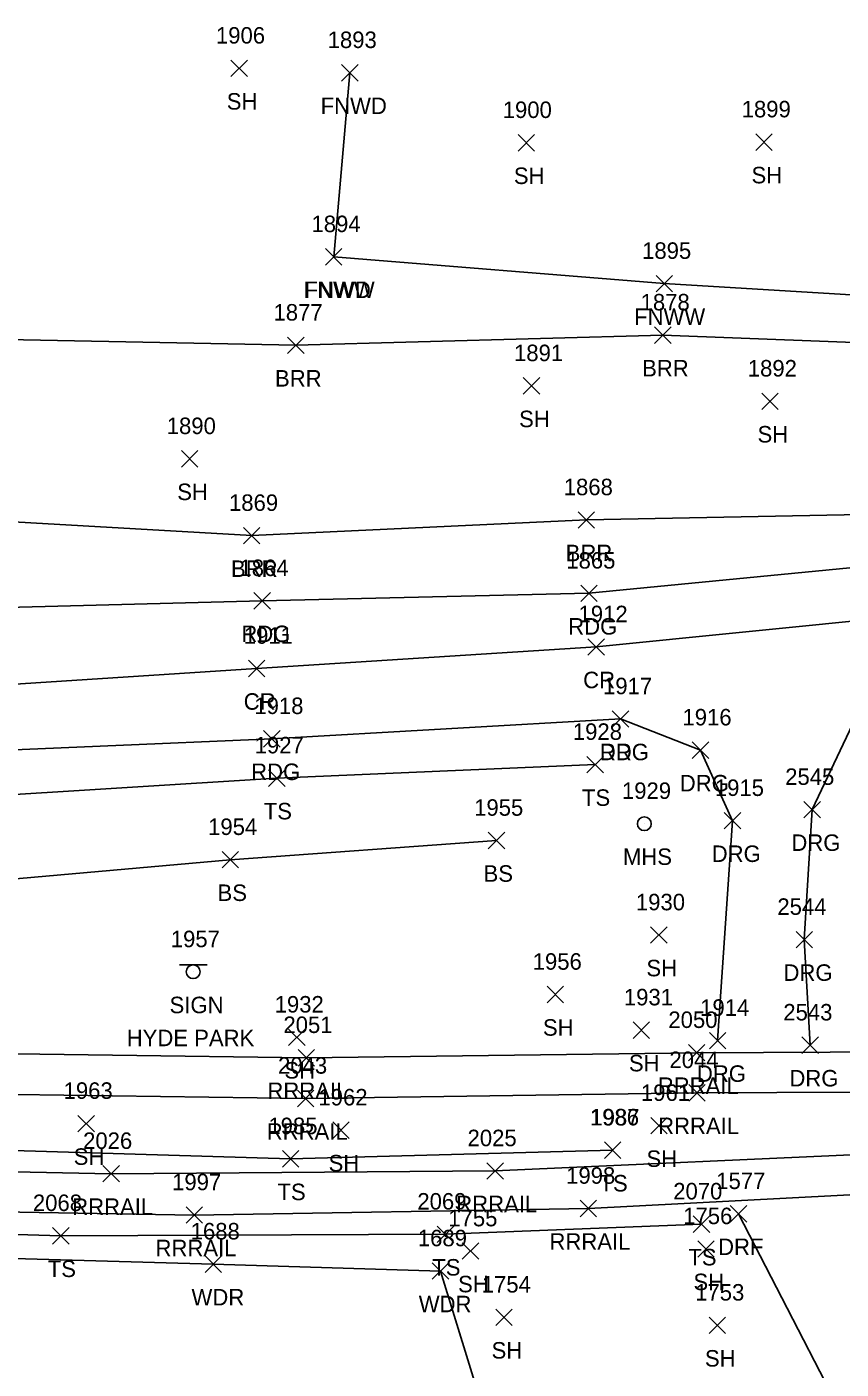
# Model space of a CAD drawing. Extents: x 1609623 to 1616187, y 756677 to 762826.
# Drawn here: x 1610145.1 to 1610243.7, y 761799.9 to 761962.6 of the extents above; entities that cross this region are included whole.
import ezdxf

# ---------------------------------------------------------------- set-up
doc = ezdxf.new("R2010")
doc.units = 0
for name, color, linetype in [('L_A', 7, 'Continuous'), ('L_I', 7, 'Continuous'), ('L_TIC', 7, 'Continuous'), ('LABL', 7, 'Continuous'), ('LAWA', 7, 'Continuous'), ('LELB', 7, 'Continuous'), ('LFNC', 7, 'Continuous'), ('P_A', 7, 'Continuous'), ('P_I', 7, 'Continuous'), ('P_TIC', 7, 'Continuous'), ('PEU', 7, 'Continuous'), ('PRC', 7, 'Continuous'), ('R_A', 7, 'Continuous'), ('R_I', 7, 'Continuous'), ('R_TIC', 7, 'Continuous'), ('RDF', 7, 'Continuous'), ('RDG', 7, 'Continuous'), ('RR', 7, 'Continuous'), ('S_A', 7, 'Continuous'), ('S_C', 7, 'Continuous'), ('S_I', 7, 'Continuous'), ('SSGN', 7, 'Continuous'), ('U_A', 7, 'Continuous'), ('U_I', 7, 'Continuous'), ('USMH', 7, 'Continuous')]:
    doc.layers.add(name, color=color, linetype=linetype)

msp = doc.modelspace()

# ---------------------------------------------------------------- linework, layer by layer
at = {"layer": 'L_TIC'}
for points in [[(1610169.82, 761956.59), (1610171.82, 761958.59)], [(1610171.82, 761956.59), (1610169.82, 761958.59)], [(1610183.22, 761956.05), (1610185.22, 761958.05)], [(1610185.22, 761956.05), (1610183.22, 761958.05)], [(1610204.59, 761947.57), (1610206.59, 761949.57)], [(1610206.59, 761947.57), (1610204.59, 761949.57)], [(1610233.37, 761947.65), (1610235.37, 761949.65)], [(1610235.37, 761947.65), (1610233.37, 761949.65)], [(1610181.26, 761933.74), (1610183.26, 761935.74)], [(1610183.26, 761933.74), (1610181.26, 761935.74)], [(1610181.26, 761933.74), (1610183.26, 761935.74)], [(1610183.26, 761933.74), (1610181.26, 761935.74)], [(1610221.3, 761930.5), (1610223.3, 761932.5)], [(1610223.3, 761930.5), (1610221.3, 761932.5)], [(1610221.12, 761924.25), (1610223.12, 761926.25)], [(1610223.12, 761924.25), (1610221.12, 761926.25)], [(1610176.67, 761923.02), (1610178.67, 761925.02)], [(1610178.67, 761923.02), (1610176.67, 761925.02)], [(1610205.22, 761918.1), (1610207.22, 761920.1)], [(1610207.22, 761918.1), (1610205.22, 761920.1)], [(1610234.1, 761916.24), (1610236.1, 761918.24)], [(1610236.1, 761916.24), (1610234.1, 761918.24)], [(1610163.82, 761909.26), (1610165.82, 761911.26)], [(1610165.82, 761909.26), (1610163.82, 761911.26)], [(1610211.86, 761901.85), (1610213.86, 761903.85)], [(1610213.86, 761901.85), (1610211.86, 761903.85)], [(1610171.33, 761899.95), (1610173.33, 761901.95)], [(1610173.33, 761899.95), (1610171.33, 761901.95)], [(1610212.92, 761872.2), (1610214.92, 761874.2)], [(1610214.92, 761872.2), (1610212.92, 761874.2)], [(1610174.38, 761870.56), (1610176.38, 761872.56)], [(1610176.38, 761870.56), (1610174.38, 761872.56)], [(1610200.97, 761863), (1610202.97, 761865)], [(1610202.97, 761863), (1610200.97, 761865)], [(1610168.74, 761860.67), (1610170.74, 761862.67)], [(1610170.74, 761860.67), (1610168.74, 761862.67)], [(1610220.64, 761851.54), (1610222.64, 761853.54)], [(1610222.64, 761851.54), (1610220.64, 761853.54)], [(1610208.11, 761844.34), (1610210.11, 761846.34)], [(1610210.11, 761844.34), (1610208.11, 761846.34)], [(1610176.8, 761839.15), (1610178.8, 761841.15)], [(1610178.8, 761839.15), (1610176.8, 761841.15)], [(1610218.52, 761840.02), (1610220.52, 761842.02)], [(1610220.52, 761840.02), (1610218.52, 761842.02)], [(1610151.29, 761828.69), (1610153.29, 761830.69)], [(1610153.29, 761828.69), (1610151.29, 761830.69)], [(1610182.15, 761827.89), (1610184.15, 761829.89)], [(1610184.15, 761827.89), (1610182.15, 761829.89)], [(1610220.65, 761828.44), (1610222.65, 761830.44)], [(1610222.65, 761828.44), (1610220.65, 761830.44)], [(1610176.04, 761824.41), (1610178.04, 761826.41)], [(1610178.04, 761824.41), (1610176.04, 761826.41)], [(1610215.04, 761825.47), (1610217.04, 761827.47)], [(1610217.04, 761825.47), (1610215.04, 761827.47)], [(1610215.04, 761825.46), (1610217.04, 761827.46)], [(1610217.04, 761825.46), (1610215.04, 761827.46)], [(1610225.8, 761816.5), (1610227.8, 761818.5)], [(1610227.8, 761816.5), (1610225.8, 761818.5)], [(1610148.22, 761815.09), (1610150.22, 761817.09)], [(1610150.22, 761815.09), (1610148.22, 761817.09)], [(1610194.79, 761815.27), (1610196.79, 761817.27)], [(1610196.79, 761815.27), (1610194.79, 761817.27)], [(1610197.83, 761813.24), (1610199.83, 761815.24)], [(1610199.83, 761813.24), (1610197.83, 761815.24)], [(1610226.34, 761813.5), (1610228.34, 761815.5)], [(1610228.34, 761813.5), (1610226.34, 761815.5)], [(1610166.68, 761811.65), (1610168.68, 761813.65)], [(1610168.68, 761811.65), (1610166.68, 761813.65)], [(1610194.19, 761810.82), (1610196.19, 761812.82)], [(1610196.19, 761810.82), (1610194.19, 761812.82)], [(1610201.89, 761805.21), (1610203.89, 761807.21)], [(1610203.89, 761805.21), (1610201.89, 761807.21)], [(1610227.73, 761804.24), (1610229.73, 761806.24)], [(1610229.73, 761804.24), (1610227.73, 761806.24)]]:
    msp.add_lwpolyline(points, dxfattribs=at)
at = {"layer": 'LABL'}
msp.add_lwpolyline([(1610248.25, 761903.55), (1610212.86, 761902.85), (1610172.33, 761900.95), (1610131.44, 761903.3), (1610100.93, 761896.76), (1610074.3, 761892.77), (1610070.02, 761901.24), (1610088.05, 761924.14), (1610103.11, 761932.23), (1610130.22, 761924.96), (1610177.67, 761924.02), (1610222.12, 761925.25), (1610272.69, 761923.3), (1610298.02, 761931.54), (1610307.47, 761946.97), (1610343.23, 761952.19), (1610333.93, 761931.55), (1610306.47, 761919.59), (1610275.72, 761908.1)], dxfattribs=at)
at = {"layer": 'LAWA'}
msp.add_lwpolyline([(1610105.26, 761813.02), (1610140.61, 761813.42), (1610167.68, 761812.65), (1610195.19, 761811.82), (1610200.47, 761794.62), (1610201.65, 761767.6), (1610187.83, 761765.14), (1610147.91, 761771.28), (1610109.49, 761778.29), (1610068.49, 761778.93), (1610059.44, 761777.35), (1610050.54, 761771.19), (1610026.67, 761771.55), (1610012.41, 761775.03), (1609988.62, 761770.46), (1609964.66, 761759.68), (1609934.55, 761749.72), (1609900.52, 761743.76), (1609861.36, 761735.79), (1609834.63, 761731.47), (1609803.94, 761726.14)], dxfattribs=at)
at = {"layer": 'LELB'}
for points in [[(1610013.78, 761861.49), (1610053.03, 761867.24), (1610097.84, 761870.5), (1610137.8, 761869.22), (1610175.38, 761871.56), (1610213.92, 761873.2)], [(1609808.99, 761869.38), (1609856.47, 761857.61), (1609895.17, 761849.99), (1609941.57, 761842.59), (1609980.54, 761837.23), (1610021.92, 761832.42), (1610061.45, 761828.82), (1610098.2, 761827.1), (1610138.02, 761826.61), (1610177.04, 761825.41), (1610216.04, 761826.47), (1610216.04, 761826.46)], [(1610091.03, 761859.31), (1610128.23, 761857.97), (1610169.74, 761861.67), (1610201.97, 761864)], [(1609853.79, 761850.29), (1609899.31, 761840.85), (1609947.61, 761833.03), (1609998.93, 761826.28), (1610045.2, 761821.51), (1610074.6, 761819.05), (1610109.29, 761817.31), (1610149.22, 761816.09), (1610195.79, 761816.27), (1610226.8, 761817.5)]]:
    msp.add_lwpolyline(points, dxfattribs=at)
at = {"layer": 'LFNC'}
for points in [[(1610184.22, 761957.05), (1610182.26, 761934.74)], [(1610182.26, 761934.74), (1610222.3, 761931.5), (1610278.21, 761928.1), (1610278.74, 761949.49)]]:
    msp.add_lwpolyline(points, dxfattribs=at)
at = {"layer": 'P_TIC'}
for points in [[(1610212.17, 761892.96), (1610214.17, 761894.96)], [(1610214.17, 761892.96), (1610212.17, 761894.96)], [(1610172.59, 761892.05), (1610174.59, 761894.05)], [(1610174.59, 761892.05), (1610172.59, 761894.05)], [(1610213.04, 761886.46), (1610215.04, 761888.46)], [(1610215.04, 761886.46), (1610213.04, 761888.46)], [(1610171.93, 761883.85), (1610173.93, 761885.85)], [(1610173.93, 761883.85), (1610171.93, 761885.85)], [(1610216, 761877.73), (1610218, 761879.73)], [(1610218, 761877.73), (1610216, 761879.73)], [(1610173.77, 761875.33), (1610175.77, 761877.33)], [(1610175.77, 761875.33), (1610173.77, 761877.33)]]:
    msp.add_lwpolyline(points, dxfattribs=at)
at = {"layer": 'PEU'}
for points in [[(1610061.53, 761886.05), (1610095.83, 761889.43), (1610133.36, 761892.01), (1610173.59, 761893.05), (1610213.17, 761893.96), (1610248.92, 761897.46)], [(1610217, 761878.73), (1610174.77, 761876.33), (1610133.16, 761874.56), (1610094.41, 761873.65), (1610052.62, 761869.93), (1610013.35, 761867.91)]]:
    msp.add_lwpolyline(points, dxfattribs=at)
at = {"layer": 'PRC'}
msp.add_lwpolyline([(1610012.87, 761874.99), (1610052.18, 761877.05), (1610092.88, 761880.29), (1610131.85, 761882.19), (1610172.93, 761884.85), (1610214.04, 761887.46), (1610250.72, 761891.17)], dxfattribs=at)
at = {"layer": 'R_TIC'}
for points in [[(1610216, 761877.73), (1610218, 761879.73)], [(1610218, 761877.73), (1610216, 761879.73)], [(1610225.68, 761873.95), (1610227.68, 761875.95)], [(1610227.68, 761873.95), (1610225.68, 761875.95)], [(1610239.2, 761866.74), (1610241.2, 761868.74)], [(1610241.2, 761866.74), (1610239.2, 761868.74)], [(1610229.55, 761865.4), (1610231.55, 761867.4)], [(1610231.55, 761865.4), (1610229.55, 761867.4)], [(1610238.25, 761850.99), (1610240.25, 761852.99)], [(1610240.25, 761850.99), (1610238.25, 761852.99)], [(1610225.22, 761837.28), (1610227.22, 761839.28)], [(1610227.22, 761837.28), (1610225.22, 761839.28)], [(1610227.76, 761838.75), (1610229.76, 761840.75)], [(1610229.76, 761838.75), (1610227.76, 761840.75)], [(1610238.97, 761838.19), (1610240.97, 761840.19)], [(1610240.97, 761838.19), (1610238.97, 761840.19)], [(1610177.94, 761836.67), (1610179.94, 761838.67)], [(1610179.94, 761836.67), (1610177.94, 761838.67)], [(1610225.26, 761832.42), (1610227.26, 761834.42)], [(1610227.26, 761832.42), (1610225.26, 761834.42)], [(1610177.86, 761831.74), (1610179.86, 761833.74)], [(1610179.86, 761831.74), (1610177.86, 761833.74)], [(1610154.3, 761822.62), (1610156.3, 761824.62)], [(1610156.3, 761822.62), (1610154.3, 761824.62)], [(1610200.81, 761822.95), (1610202.81, 761824.95)], [(1610202.81, 761822.95), (1610200.81, 761824.95)], [(1610212.1, 761818.4), (1610214.1, 761820.4)], [(1610214.1, 761818.4), (1610212.1, 761820.4)], [(1610230.28, 761817.76), (1610232.28, 761819.76)], [(1610232.28, 761817.76), (1610230.28, 761819.76)], [(1610164.38, 761817.61), (1610166.38, 761819.61)], [(1610166.38, 761817.61), (1610164.38, 761819.61)]]:
    msp.add_lwpolyline(points, dxfattribs=at)
at = {"layer": 'RDF'}
msp.add_lwpolyline([(1610264.31, 761756.11), (1610264.09, 761770.09), (1610248.38, 761785.61), (1610231.28, 761818.76)], dxfattribs=at)
at = {"layer": 'RDG'}
for points in [[(1610239.97, 761839.19), (1610239.25, 761851.99), (1610240.2, 761867.74), (1610246.98, 761882.07)], [(1610228.76, 761839.75), (1610230.55, 761866.4), (1610226.68, 761874.95), (1610217, 761878.73)]]:
    msp.add_lwpolyline(points, dxfattribs=at)
at = {"layer": 'RR'}
for points in [[(1610920.34, 761877.5), (1610875.2, 761880.63), (1610823.88, 761880.35), (1610770.14, 761877.16), (1610718.25, 761872.56), (1610624.39, 761862.75), (1610528.95, 761852.85), (1610433.45, 761843.38), (1610390.08, 761839.1), (1610343.15, 761834.31), (1610326.86, 761832.49), (1610295.2, 761829.73), (1610250.28, 761826.15), (1610201.81, 761823.95), (1610155.3, 761823.62), (1610106.26, 761824.63), (1610057.65, 761827.02), (1610007.52, 761831.91), (1609961.32, 761837.48), (1609915.47, 761844.69), (1609871.57, 761853.1), (1609828.18, 761862.73), (1609811.27, 761866.9)], [(1610356.77, 761837.2), (1610311.16, 761837.59), (1610274.66, 761838.51), (1610226.22, 761838.28), (1610178.94, 761837.67), (1610131.97, 761838.32), (1610083.45, 761840.67), (1610036.86, 761844.06), (1609989.49, 761848.51), (1609944.78, 761853.81), (1609900.87, 761860.46), (1609856.95, 761868.77), (1609813.49, 761878.61)], [(1609812.23, 761861.59), (1609849.51, 761852.68), (1609889.11, 761844.53), (1609934.67, 761836.61), (1609980.82, 761829.97), (1610026.24, 761824.91), (1610071.82, 761821.22), (1610118.39, 761819.39), (1610165.38, 761818.61), (1610213.1, 761819.4), (1610261.76, 761821.96), (1610309.94, 761826.07), (1610356.6, 761830.72), (1610389.15, 761834), (1610434.7, 761838.51), (1610480.7, 761843.13), (1610575.97, 761852.51), (1610672.94, 761862.83), (1610719.08, 761867.65), (1610767.25, 761871.97), (1610815.87, 761875.05), (1610864.69, 761875.82), (1610894.81, 761874.78)], [(1609812.59, 761873.79), (1609856.08, 761863.93), (1609900.7, 761855.53), (1609944.64, 761848.95), (1609989.39, 761843.6), (1610036.39, 761839.13), (1610083.14, 761835.83), (1610131.98, 761833.39), (1610178.86, 761832.74), (1610226.26, 761833.42), (1610274.6, 761833.63)]]:
    msp.add_lwpolyline(points, dxfattribs=at)
at = {"layer": 'SSGN'}
for p, q in [((1610163.59, 761848.92), (1610166.92, 761848.92)), ((1610165.24, 761848.09), (1610165.24, 761848.09))]:
    msp.add_line(p, q, dxfattribs=at)
msp.add_circle((1610165.24, 761848.09), 0.833, dxfattribs=at)
at = {"layer": 'USMH'}
for p, q in [((1610219.88, 761866.04), (1610219.88, 761866.04)), ((1610220.71, 761866.04), (1610220.71, 761866.04))]:
    msp.add_line(p, q, dxfattribs=at)
msp.add_circle((1610219.88, 761866.04), 0.833, dxfattribs=at)

# ---------------------------------------------------------------- texts
at = {"layer": 'L_A'}
for s, p in [('SH', (1610169.31, 761952.59)), ('FNWD', (1610180.68, 761952.05)), ('SH', (1610204.08, 761943.57)), ('SH', (1610232.86, 761943.65)), ('FNWW', (1610178.61, 761929.74)), ('FNWD', (1610178.73, 761929.74)), ('FNWW', (1610218.64, 761926.5)), ('BRR', (1610219.61, 761920.25)), ('BRR', (1610175.15, 761919.02)), ('SH', (1610204.71, 761914.1)), ('SH', (1610233.59, 761912.24)), ('SH', (1610163.31, 761905.26)), ('BRR', (1610210.35, 761897.85)), ('BRR', (1610169.82, 761895.95)), ('TS', (1610212.33, 761868.2)), ('TS', (1610173.79, 761866.56)), ('BS', (1610200.41, 761859)), ('BS', (1610168.19, 761856.67)), ('SH', (1610220.13, 761847.54)), ('SH', (1610207.6, 761840.34)), ('SH', (1610218.01, 761836.02)), ('SH', (1610176.29, 761835.15)), ('SH', (1610150.77, 761824.69)), ('SH', (1610220.14, 761824.44)), ('SH', (1610181.64, 761823.89)), ('TS', (1610214.45, 761821.47)), ('TS', (1610214.45, 761821.46)), ('TS', (1610175.45, 761820.41)), ('TS', (1610194.2, 761811.27)), ('TS', (1610225.21, 761812.5)), ('TS', (1610147.63, 761811.09)), ('SH', (1610197.32, 761809.24)), ('SH', (1610225.83, 761809.5)), ('WDR', (1610165.04, 761807.65)), ('WDR', (1610192.56, 761806.82)), ('SH', (1610201.38, 761801.21)), ('SH', (1610227.22, 761800.24))]:
    msp.add_text(s, height=2, dxfattribs=at).set_placement(p)
at = {"layer": 'L_I'}
for s, p in [('1906', (1610168, 761960.59)), ('1893', (1610181.53, 761960.05)), ('1900', (1610202.73, 761951.57)), ('1899', (1610231.67, 761951.65)), ('1894', (1610179.57, 761937.74)), ('1894', (1610179.57, 761937.74)), ('1895', (1610219.61, 761934.5)), ('1877', (1610174.97, 761927.02)), ('1878', (1610219.43, 761928.25)), ('1891', (1610204.1, 761922.1)), ('1892', (1610232.41, 761920.24)), ('1890', (1610162.04, 761913.26)), ('1868', (1610210.12, 761905.85)), ('1869', (1610169.58, 761903.95)), ('1928', (1610211.22, 761876.2)), ('1927', (1610172.69, 761874.56)), ('1955', (1610199.27, 761867)), ('1954', (1610167.05, 761864.67)), ('1930', (1610218.86, 761855.54)), ('1956', (1610206.36, 761848.34)), ('1931', (1610217.4, 761844.02)), ('1932', (1610175.11, 761843.15)), ('1963', (1610149.55, 761832.69)), ('1961', (1610219.47, 761832.44)), ('1962', (1610180.41, 761831.89)), ('1986', (1610213.29, 761829.47)), ('1987', (1610213.35, 761829.46)), ('1985', (1610174.35, 761828.41)), ('2070', (1610223.38, 761820.5)), ('2068', (1610145.83, 761819.09)), ('2069', (1610192.39, 761819.27)), ('1755', (1610196.14, 761817.24)), ('1756', (1610224.59, 761817.5)), ('1688', (1610164.94, 761815.65)), ('1689', (1610192.45, 761814.82)), ('1754', (1610200.19, 761809.21)), ('1753', (1610226.04, 761808.24))]:
    msp.add_text(s, height=2, dxfattribs=at).set_placement(p)
at = {"layer": 'P_A'}
for s, p in [('RDG', (1610171.08, 761888.05)), ('RDG', (1610210.66, 761888.96)), ('CR', (1610212.47, 761882.46)), ('CR', (1610171.36, 761879.85)), ('RDG', (1610214.49, 761873.73)), ('RDG', (1610172.26, 761871.33))]:
    msp.add_text(s, height=2, dxfattribs=at).set_placement(p)
at = {"layer": 'P_I'}
for s, p in [('1864', (1610170.85, 761896.05)), ('1865', (1610210.43, 761896.96)), ('1912', (1610211.91, 761890.46)), ('1911', (1610171.37, 761887.85)), ('1917', (1610214.88, 761881.73)), ('1918', (1610172.65, 761879.33))]:
    msp.add_text(s, height=2, dxfattribs=at).set_placement(p)
at = {"layer": 'R_A'}
for s, p in [('DRG', (1610214.49, 761873.73)), ('DRG', (1610224.17, 761869.95)), ('DRG', (1610237.69, 761862.74)), ('DRG', (1610228.04, 761861.4)), ('DRG', (1610236.73, 761846.99)), ('DRG', (1610226.25, 761834.75)), ('DRG', (1610237.45, 761834.19)), ('RRRAIL', (1610174.23, 761832.67)), ('RRRAIL', (1610221.51, 761833.28)), ('RRRAIL', (1610174.15, 761827.74)), ('RRRAIL', (1610221.55, 761828.42)), ('RRRAIL', (1610150.59, 761818.62)), ('RRRAIL', (1610197.1, 761818.95)), ('RRRAIL', (1610160.68, 761813.61)), ('RRRAIL', (1610208.39, 761814.4)), ('DRF', (1610228.81, 761813.76))]:
    msp.add_text(s, height=2, dxfattribs=at).set_placement(p)
at = {"layer": 'R_I'}
for s, p in [('1917', (1610214.88, 761881.73)), ('1916', (1610224.5, 761877.95)), ('2545', (1610236.94, 761870.74)), ('1915', (1610228.42, 761869.4)), ('2544', (1610235.99, 761854.99)), ('1914', (1610226.64, 761842.75)), ('2543', (1610236.71, 761842.19)), ('2051', (1610176.17, 761840.67)), ('2050', (1610222.79, 761841.28)), ('2043', (1610175.52, 761835.74)), ('2044', (1610222.92, 761836.42)), ('2026', (1610151.91, 761826.62)), ('2025', (1610198.47, 761826.95)), ('1997', (1610162.69, 761821.61)), ('1998', (1610210.41, 761822.4)), ('1577', (1610228.59, 761821.76))]:
    msp.add_text(s, height=2, dxfattribs=at).set_placement(p)
at = {"layer": 'S_A'}
msp.add_text('SIGN', height=2, dxfattribs=at).set_placement((1610162.38, 761843.07))
at = {"layer": 'S_C'}
msp.add_text('HYDE PARK', height=2, dxfattribs=at).set_placement((1610157.19, 761839.07))
at = {"layer": 'S_I'}
msp.add_text('1957', height=2, dxfattribs=at).set_placement((1610162.53, 761851.07))
at = {"layer": 'U_A'}
msp.add_text('MHS', height=2, dxfattribs=at).set_placement((1610217.29, 761861.04))
at = {"layer": 'U_I'}
msp.add_text('1929', height=2, dxfattribs=at).set_placement((1610217.17, 761869.04))

doc.saveas('drawing.dxf')
